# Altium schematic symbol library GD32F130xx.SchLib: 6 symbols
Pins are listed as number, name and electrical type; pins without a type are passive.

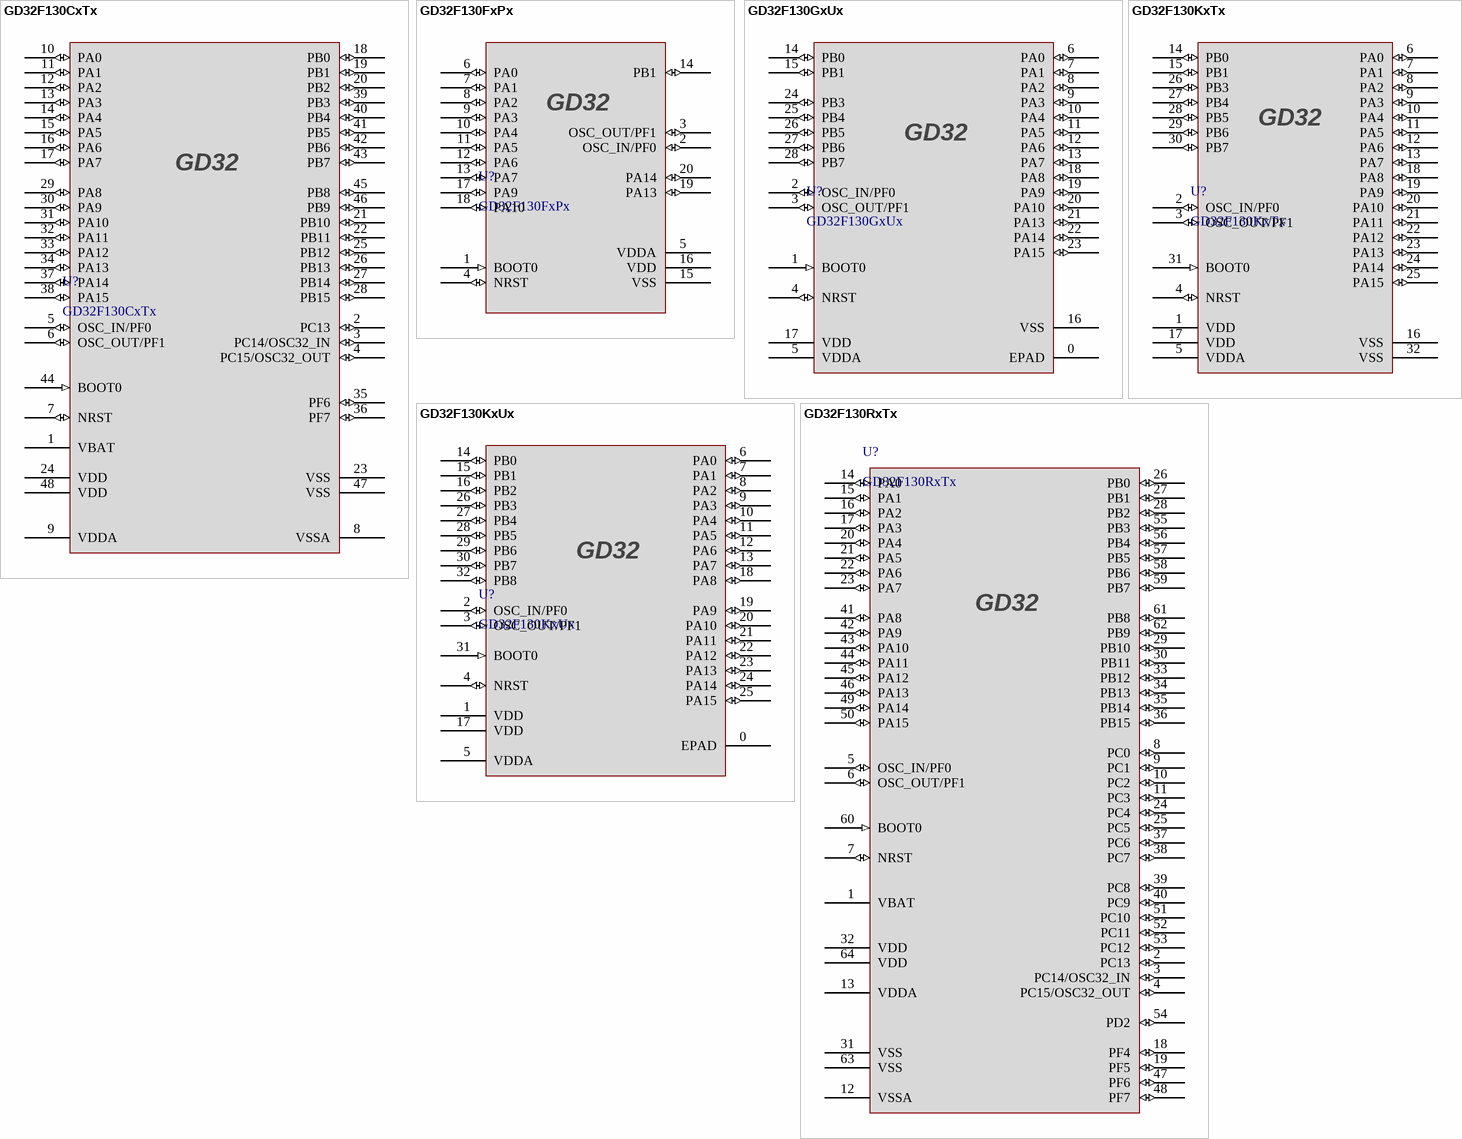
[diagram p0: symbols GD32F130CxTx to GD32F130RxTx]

## GD32F130CxTx
designator U?
footprint LQFP48_7x7x1.6
pins: 1 VBAT (power), 2 PC13 (io), 3 PC14/OSC32_IN (io), 4 PC15/OSC32_OUT (io), 5 OSC_IN/PF0 (io), 6 OSC_OUT/PF1 (io), 7 NRST (io), 8 VSSA (power), 9 VDDA (power), 10 PA0 (io), 11 PA1 (io), 12 PA2 (io), 13 PA3 (io), 14 PA4 (io), 15 PA5 (io), 16 PA6 (io), 17 PA7 (io), 18 PB0 (io), 19 PB1 (io), 20 PB2 (io), 21 PB10 (io), 22 PB11 (io), 23 VSS (power), 24 VDD (power), 25 PB12 (io), 26 PB13 (io), 27 PB14 (io), 28 PB15 (io), 29 PA8 (io), 30 PA9 (io), 31 PA10 (io), 32 PA11 (io), 33 PA12 (io), 34 PA13 (io), 35 PF6 (io), 36 PF7 (io), 37 PA14 (io), 38 PA15 (io), 39 PB3 (io), 40 PB4 (io), 41 PB5 (io), 42 PB6 (io), 43 PB7 (io), 44 BOOT0 (in), 45 PB8 (io), 46 PB9 (io), 47 VSS (power), 48 VDD (power)

## GD32F130FxPx
designator U?
footprint TSSOP20-4.5x6.6x1.2
pins: 1 BOOT0 (in), 2 OSC_IN/PF0 (io), 3 OSC_OUT/PF1 (io), 4 NRST (io), 5 VDDA (power), 6 PA0 (io), 7 PA1 (io), 8 PA2 (io), 9 PA3 (io), 10 PA4 (io), 11 PA5 (io), 12 PA6 (io), 13 PA7 (io), 14 PB1 (io), 15 VSS (power), 16 VDD (power), 17 PA9 (io), 18 PA10 (io), 19 PA13 (io), 20 PA14 (io)

## GD32F130GxUx
designator U?
footprint QFN28_4X4X0.8
pins: 0 EPAD (power), 1 BOOT0 (in), 2 OSC_IN/PF0 (io), 3 OSC_OUT/PF1 (io), 4 NRST (io), 5 VDDA (power), 6 PA0 (io), 7 PA1 (io), 8 PA2 (io), 9 PA3 (io), 10 PA4 (io), 11 PA5 (io), 12 PA6 (io), 13 PA7 (io), 14 PB0 (io), 15 PB1 (io), 16 VSS (power), 17 VDD (power), 18 PA8 (io), 19 PA9 (io), 20 PA10 (io), 21 PA13 (io), 22 PA14 (io), 23 PA15 (io), 24 PB3 (io), 25 PB4 (io), 26 PB5 (io), 27 PB6 (io), 28 PB7 (io)

## GD32F130KxTx
designator U?
footprint LQFP32_7x7X1.6
pins: 1 VDD (power), 2 OSC_IN/PF0 (io), 3 OSC_OUT/PF1 (io), 4 NRST (io), 5 VDDA (power), 6 PA0 (io), 7 PA1 (io), 8 PA2 (io), 9 PA3 (io), 10 PA4 (io), 11 PA5 (io), 12 PA6 (io), 13 PA7 (io), 14 PB0 (io), 15 PB1 (io), 16 VSS (power), 17 VDD (power), 18 PA8 (io), 19 PA9 (io), 20 PA10 (io), 21 PA11 (io), 22 PA12 (io), 23 PA13 (io), 24 PA14 (io), 25 PA15 (io), 26 PB3 (io), 27 PB4 (io), 28 PB5 (io), 29 PB6 (io), 30 PB7 (io), 31 BOOT0 (in), 32 VSS (power)

## GD32F130KxUx
designator U?
footprint QFN32_5X5X0.8
pins: 0 EPAD (power), 1 VDD (power), 2 OSC_IN/PF0 (io), 3 OSC_OUT/PF1 (io), 4 NRST (io), 5 VDDA (power), 6 PA0 (io), 7 PA1 (io), 8 PA2 (io), 9 PA3 (io), 10 PA4 (io), 11 PA5 (io), 12 PA6 (io), 13 PA7 (io), 14 PB0 (io), 15 PB1 (io), 16 PB2 (io), 17 VDD (power), 18 PA8 (io), 19 PA9 (io), 20 PA10 (io), 21 PA11 (io), 22 PA12 (io), 23 PA13 (io), 24 PA14 (io), 25 PA15 (io), 26 PB3 (io), 27 PB4 (io), 28 PB5 (io), 29 PB6 (io), 30 PB7 (io), 31 BOOT0 (in), 32 PB8 (io)

## GD32F130RxTx
designator U?
footprint LQPF64_10x10x1.6
pins: 1 VBAT (power), 2 PC13 (io), 3 PC14/OSC32_IN (io), 4 PC15/OSC32_OUT (io), 5 OSC_IN/PF0 (io), 6 OSC_OUT/PF1 (io), 7 NRST (io), 8 PC0 (io), 9 PC1 (io), 10 PC2 (io), 11 PC3 (io), 12 VSSA (power), 13 VDDA (power), 14 PA0 (io), 15 PA1 (io), 16 PA2 (io), 17 PA3 (io), 18 PF4 (io), 19 PF5 (io), 20 PA4 (io), 21 PA5 (io), 22 PA6 (io), 23 PA7 (io), 24 PC4 (io), 25 PC5 (io), 26 PB0 (io), 27 PB1 (io), 28 PB2 (io), 29 PB10 (io), 30 PB11 (io), 31 VSS (power), 32 VDD (power), 33 PB12 (io), 34 PB13 (io), 35 PB14 (io), 36 PB15 (io), 37 PC6 (io), 38 PC7 (io), 39 PC8 (io), 40 PC9 (io), 41 PA8 (io), 42 PA9 (io), 43 PA10 (io), 44 PA11 (io), 45 PA12 (io), 46 PA13 (io), 47 PF6 (io), 48 PF7 (io), 49 PA14 (io), 50 PA15 (io), 51 PC10 (io), 52 PC11 (io), 53 PC12 (io), 54 PD2 (io), 55 PB3 (io), 56 PB4 (io), 57 PB5 (io), 58 PB6 (io), 59 PB7 (io), 60 BOOT0 (in), 61 PB8 (io), 62 PB9 (io), 63 VSS (power), 64 VDD (power)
